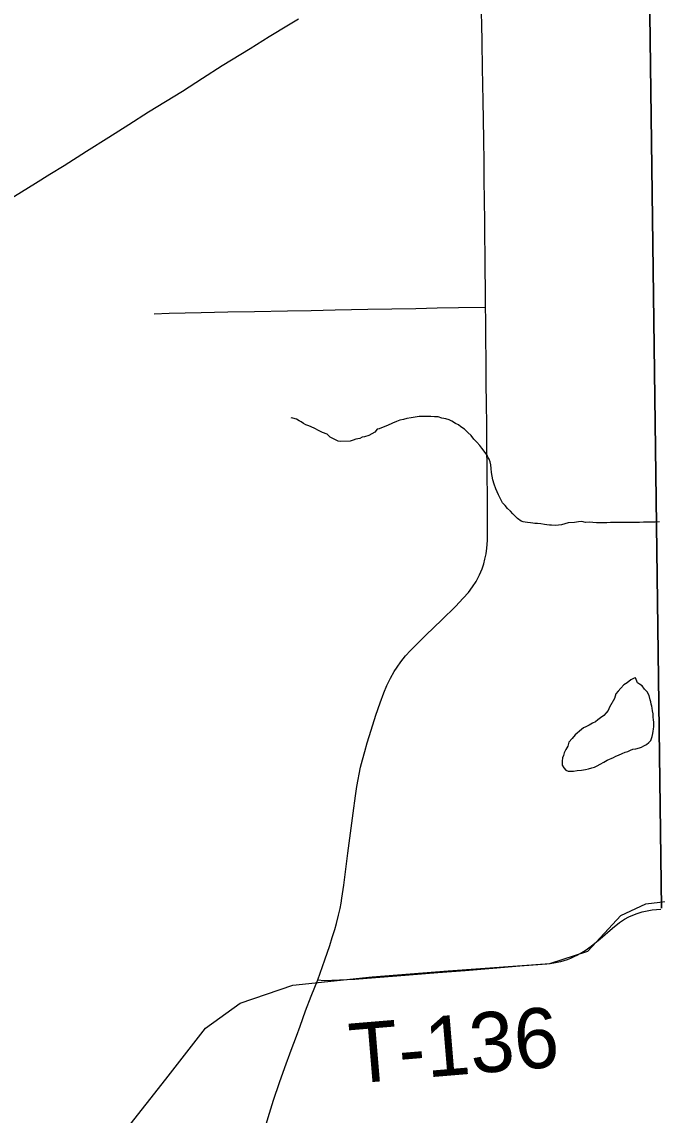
# Model space of a CAD drawing. Extents: x 103424 to 290657, y 38711 to 110967.
# Drawn here: x 146061 to 149253, y 55076 to 60565 of the extents above; entities that cross this region are included whole.
import ezdxf

# ---------------------------------------------------------------- set-up
doc = ezdxf.new("R2010")
doc.units = 0
for name, color, linetype in [('GM_X_Corporation', 7, 'Continuous'), ('GM_X_Minor_Lake', 7, 'Continuous'), ('GM_X_Minor_River', 7, 'Continuous'), ('GM_X_Rail_Line', 7, 'Continuous'), ('GM_X_State_Route', 7, 'Continuous'), ('GM_X_Township_Road', 7, 'Continuous'), ('GM_X_Township_Road_Text', 7, 'Continuous')]:
    doc.layers.add(name, color=color, linetype=linetype)

msp = doc.modelspace()

# ---------------------------------------------------------------- linework, layer by layer
at = {"layer": 'GM_X_Corporation'}
for points in [[(149274.7, 56114.3), (149214.2, 60733.4), (149097.2, 69817.3), (149097.1, 69822.5), (149073.5, 71652), (151578, 71707.7)], [(149097.2, 69817.3), (149214.2, 60733.4), (149274.7, 56114.3)]]:
    msp.add_lwpolyline(points, dxfattribs=at)
at = {"layer": 'GM_X_Minor_Lake'}
for points in [[(149144.5, 57272.3), (149138.5, 57270.1), (149120.5, 57261.6), (149102.6, 57247.1), (149086.7, 57236.7), (149070.8, 57220.2), (149057, 57203.7), (149045.2, 57191.3), (149039.6, 57167), (149014.3, 57124.1), (149006.5, 57107.7), (148996.7, 57095.4), (148984.8, 57083), (148968.9, 57070.6), (148955, 57060.2), (148943.1, 57049.8), (148929.1, 57043.5), (148911.1, 57033), (148895.1, 57024.6), (148883.1, 57020.2), (148873.2, 57012), (148863.2, 57003.7), (148851.3, 56993.3), (148841.4, 56985), (148825.6, 56966.5), (148809.9, 56948), (148804.2, 56927.7), (148794.5, 56911.3), (148786.7, 56895), (148783, 56880.8), (148777.2, 56870.6), (148775.5, 56852.4), (148776, 56832.2), (148784.3, 56820.2), (148794.7, 56808.4), (148806.9, 56802.6), (148817, 56802.8), (148833.2, 56803.1), (148851.3, 56805.5), (148873.5, 56808), (148893.6, 56810.5), (148907.7, 56814.9), (148925.8, 56819.3), (148937.8, 56823.6)], [(149144.5, 57272.3), (149138.5, 57270.1), (149120.5, 57261.6), (149102.6, 57247.1), (149086.7, 57236.7), (149070.8, 57220.2), (149057, 57203.7), (149045.2, 57191.3), (149039.6, 57167), (149014.3, 57124.1), (149006.5, 57107.7), (148996.7, 57095.4), (148984.8, 57083), (148968.9, 57070.6), (148955, 57060.2), (148943.1, 57049.8), (148929.1, 57043.5), (148911.1, 57033), (148895.1, 57024.6), (148883.1, 57020.2), (148873.2, 57012), (148863.2, 57003.7), (148851.3, 56993.3), (148841.4, 56985), (148825.6, 56966.5), (148809.9, 56948), (148804.2, 56927.7), (148794.5, 56911.3), (148786.7, 56895), (148783, 56880.8), (148777.2, 56870.6), (148775.5, 56852.4), (148776, 56832.2), (148784.3, 56820.2), (148794.7, 56808.4), (148806.9, 56802.6), (148817, 56802.8), (148833.2, 56803.1), (148851.3, 56805.5), (148873.5, 56808), (148893.6, 56810.5), (148907.7, 56814.9), (148925.8, 56819.3), (148937.8, 56823.6), (148951.8, 56829.9), (148967.8, 56838.4), (148985.8, 56848.8), (149001.8, 56857.3), (149033.8, 56872.1), (149045.8, 56878.4), (149059.8, 56882.8), (149077.8, 56891.2), (149091.9, 56897.6), (149105.9, 56901.9), (149119.9, 56908.3), (149132, 56912.6), (149146.1, 56914.9), (149164.2, 56919.4), (149174.2, 56923.6), (149186.2, 56929.9), (149200.2, 56936.3), (149212.1, 56946.7), (149222, 56957), (149225.8, 56967.1), (149227.6, 56977.3), (149231.3, 56991.5), (149233.1, 57003.6), (149234.9, 57013.8), (149236.6, 57027.9), (149236.4, 57038), (149236.2, 57048.1), (149235.9, 57060.2), (149233.6, 57074.3), (149233.3, 57090.5), (149230.9, 57106.6), (149228.6, 57118.6), (149226.4, 57128.7), (149224.1, 57138.7), (149221.9, 57150.8), (149217.6, 57160.8), (149213.1, 57182.9), (149202.6, 57200.8), (149190.2, 57214.7), (149177.7, 57230.6), (149165.4, 57240.4), (149155.2, 57246.2), (149144.5, 57272.3)], [(148937.8, 56823.6), (148951.8, 56829.9), (148967.8, 56838.4), (148985.8, 56848.8), (149001.8, 56857.3), (149033.8, 56872.1), (149045.8, 56878.4), (149059.8, 56882.8), (149077.8, 56891.2), (149091.9, 56897.6), (149105.9, 56901.9), (149119.9, 56908.3), (149132, 56912.6), (149146.1, 56914.9), (149164.2, 56919.4), (149174.2, 56923.6), (149186.2, 56929.9), (149200.2, 56936.3), (149212.1, 56946.7), (149222, 56957), (149225.8, 56967.1), (149227.6, 56977.3), (149231.3, 56991.5), (149233.1, 57003.6), (149234.9, 57013.8), (149236.6, 57027.9), (149236.4, 57038), (149236.2, 57048.1), (149235.9, 57060.2), (149233.6, 57074.3), (149233.3, 57090.5), (149230.9, 57106.6), (149228.6, 57118.6), (149226.4, 57128.7), (149224.1, 57138.7), (149221.9, 57150.8), (149217.6, 57160.8), (149213.1, 57182.9), (149202.6, 57200.8), (149190.2, 57214.7), (149177.7, 57230.6), (149165.4, 57240.4), (149155.2, 57246.2), (149144.5, 57272.3)]]:
    msp.add_lwpolyline(points, dxfattribs=at)
at = {"layer": 'GM_X_Minor_River'}
for points in [[(148134.3, 58582.8), (148116.1, 58584.4), (148095.9, 58584), (148075.7, 58583.6), (148057.5, 58583.2), (148037.4, 58580.7), (148017.3, 58576.2), (147995.1, 58573.7), (147979, 58569.4), (147960.9, 58564.9), (147942.9, 58558.5), (147922.8, 58550), (147898.8, 58539.3), (147876.8, 58530.8), (147856.7, 58522.3), (147846.7, 58520), (147834.8, 58505.6), (147804.9, 58488.8), (147782.8, 58482.3), (147770.7, 58480), (147758.7, 58473.7), (147738.6, 58469.2), (147726.6, 58464.9), (147710.5, 58460.5), (147660, 58457.4), (147649.9, 58459.2), (147633.5, 58469), (147611, 58480.6), (147594.6, 58494.3), (147572.1, 58504), (147551.7, 58513.6), (147533.3, 58523.3), (147515, 58531), (147502.7, 58536.8), (147488.5, 58542.5), (147476.2, 58548.3), (147463.9, 58556.1), (147453.7, 58561.9), (147441.4, 58569.8), (147423.1, 58575.4), (147415, 58577.3), (147415, 58575.2)], [(149265.3, 58054.2), (149243, 58053.7), (149184.5, 58052.5), (149164.3, 58052), (149144, 58051.6), (149123.9, 58051.1), (149103.7, 58050.7), (149077.4, 58052.1), (149057.1, 58051.7), (149036.9, 58051.3), (149018.8, 58050.9), (149000.6, 58050.5), (148984.4, 58050.1), (148966.2, 58049.7), (148948.1, 58049.3), (148929.8, 58051), (148911.6, 58052.6), (148893.4, 58052.2), (148875.2, 58055.8), (148859, 58055.5), (148838.9, 58051), (148806.6, 58050.3), (148772.4, 58039.5), (148742.2, 58036.8), (148721.9, 58038.4), (148711.8, 58038.1), (148699.7, 58039.9), (148687.5, 58041.7), (148669.2, 58045.3), (148653, 58047), (148638.9, 58046.7), (148628.8, 58048.4), (148616.6, 58050.2), (148602.4, 58051.9), (148590.3, 58053.7), (148580.1, 58055.5), (148570, 58057.3), (148551.5, 58071), (148541.2, 58080.9), (148528.7, 58094.7), (148516.3, 58108.6), (148501.9, 58122.4), (148489.5, 58136.3), (148477, 58150.1), (148466.5, 58170.1), (148456, 58190.1), (148443.2, 58220.1), (148434.6, 58244.1), (148428.1, 58266.2), (148423.7, 58284.2), (148421.2, 58302.4), (148418.8, 58322.5), (148418.4, 58340.7), (148414, 58356.7), (148409.7, 58368.7), (148403.4, 58378.7), (148399.2, 58388.7), (148372.2, 58424.5), (148361.7, 58438.4), (148347.3, 58454.2), (148332.8, 58470), (148318.3, 58487.9), (148301.7, 58503.7), (148285.2, 58519.5), (148266.8, 58531.2), (148254.5, 58541), (148240.2, 58548.8), (148221.7, 58560.5), (148207.5, 58566.2), (148191.2, 58571.9), (148170.9, 58575.5), (148152.6, 58581.2), (148134.3, 58582.8)]]:
    msp.add_lwpolyline(points, dxfattribs=at)
at = {"layer": 'GM_X_Rail_Line'}
msp.add_lwpolyline([(146505.7, 54902.5), (146783.9, 55255.5), (146983.2, 55513), (147157.5, 55637.6), (147423.3, 55729), (147821.8, 55770.5), (148203.8, 55799.6), (148714.5, 55836.9), (148905.5, 55899.2), (149071.5, 56077.8), (149196.1, 56136), (149366.3, 56156.7)], dxfattribs=at)
at = {"layer": 'GM_X_State_Route'}
for points in [[(148373.8, 60461.2), (148373.4, 60482.3), (148372.2, 60536.1), (148370.3, 60624), (148368.9, 60684.8), (148367.7, 60746.2), (148366.9, 60856.3), (148366.2, 60966.4), (148365.4, 61012.8)], [(145385.3, 59293), (145430.6, 59322), (145532.7, 59384.8), (145610.3, 59433.4), (145687.9, 59482.1), (145768.3, 59531.9), (145848.8, 59581.7), (145989.1, 59668.6), (146129.5, 59755.5), (146201.5, 59800.2), (146273.6, 59844.8), (146386.1, 59915.7), (146498.6, 59986.6), (146598.1, 60049.6), (146697.5, 60112.7), (146782.9, 60165.4), (146868.2, 60218), (146967.9, 60281.7), (147067.5, 60345.5), (147208, 60432.1), (147304.2, 60491.4), (147400.5, 60550.7), (147451.3, 60581)], [(145385.3, 59293), (145430.6, 59322), (145532.7, 59384.8), (145610.3, 59433.4), (145687.9, 59482.1), (145768.3, 59531.9), (145848.8, 59581.7), (145989.1, 59668.6), (146129.5, 59755.5), (146201.5, 59800.2), (146273.6, 59844.8), (146386.1, 59915.7), (146498.6, 59986.6), (146598.1, 60049.6), (146697.5, 60112.7), (146782.9, 60165.4), (146868.2, 60218), (146967.9, 60281.7), (147067.5, 60345.5), (147208, 60432.1), (147304.2, 60491.4), (147400.5, 60550.7), (147451.3, 60581)], [(147279.2, 54997.2), (147305.2, 55085.4), (147325.5, 55150.9), (147355.2, 55240.2), (147381.7, 55314.1), (147413.9, 55401.1), (147440.4, 55472.3), (147459.1, 55522.6), (147486.6, 55599.4), (147515.3, 55672.4), (147547.6, 55754.3), (147582.9, 55856.2), (147607.8, 55927.4), (147621, 55967), (147633.4, 56008.6), (147642.1, 56038.2), (147652.7, 56080.5), (147659.7, 56113), (147665, 56140.3), (147669.4, 56165.8), (147679, 56230.9), (147689.6, 56310.1), (147699.1, 56391.6), (147712.6, 56491.5), (147725.8, 56591.5), (147736.9, 56678.6), (147744.1, 56726.3), (147750.3, 56761.1), (147755.6, 56787.9), (147763.5, 56822.2), (147772.3, 56860), (147783.8, 56901.4), (147796.1, 56944.5), (147816.5, 57008.7), (147840.4, 57084.1), (147862, 57145.1), (147880.4, 57195.5), (147895.5, 57233.1), (147913.1, 57270.1), (147932.4, 57302.6), (147947.4, 57325.5), (147965.9, 57351.9), (147989.6, 57381.8), (148014.3, 57409.1), (148090.7, 57484.9), (148171.4, 57562.9), (148240, 57629.2), (148278, 57671.1), (148304.9, 57700.6), (148325.7, 57727.6), (148344.2, 57755.7), (148360.9, 57789.2), (148373.3, 57819.1), (148382.1, 57843.7), (148388, 57866.8), (148393.4, 57893.3), (148397.8, 57922.3), (148401, 57960.2), (148401.6, 57989.6), (148401.1, 58082.5), (148400.7, 58175.4), (148399.6, 58296), (148398, 58458.7), (148397.1, 58545), (148396.1, 58645.3), (148395, 58751.7), (148394, 58854.7), (148392.6, 58984.9), (148391.8, 59068.5), (148391.2, 59132.2), (148390.1, 59228.6), (148389.2, 59316.6), (148388.7, 59400.7), (148388.2, 59484.7), (148387.3, 59564.7), (148386, 59667.7), (148384.8, 59772.4), (148383.7, 59862.1), (148382.4, 59972.1), (148381.2, 60074.2), (148379.4, 60166.6), (148377.8, 60250.5), (148376.2, 60334.5), (148373.8, 60461.2)]]:
    msp.add_lwpolyline(points, dxfattribs=at)
at = {"layer": 'GM_X_Township_Road'}
for points in [[(146725.3, 59099.3), (146800.9, 59102.8), (146962.4, 59105.9), (147096.3, 59108.5), (147230.1, 59111.1), (147395.1, 59114.3), (147515.1, 59116.6), (147635, 59118.9), (147800.1, 59122.1), (147920.3, 59124.4), (148040.6, 59126.7), (148147.8, 59128.8), (148254.9, 59130.8), (148391.2, 59132.2)], [(147547.6, 55754.3), (147580.3, 55752.3), (147734.3, 55758.9), (147860.5, 55768.3), (147986.7, 55777.8), (148151.2, 55791.1), (148289.5, 55802.3), (148427.6, 55813.6), (148563.2, 55824.6), (148698.7, 55835.5), (148716.6, 55837.3), (148734.2, 55839.9), (148751.6, 55843.2), (148769, 55847.3), (148785.9, 55852.3), (148802.7, 55858), (148819.3, 55864.4), (148835.7, 55871.6), (148851.6, 55879.5), (148866.9, 55888.1), (148891.7, 55902.1), (148921.8, 55923.7), (148966.4, 55960.4), (149029.2, 56014.4), (149064.7, 56042.3), (149090.2, 56059.3), (149111.9, 56070.9), (149130.8, 56079.6), (149153.7, 56088.8), (149178.4, 56096.5), (149195, 56100.5), (149211.9, 56103.6), (149229, 56106), (149249.4, 56108.4), (149271.7, 56109.1)]]:
    msp.add_lwpolyline(points, dxfattribs=at)

# ---------------------------------------------------------------- texts
at = {"layer": 'GM_X_Township_Road_Text'}
msp.add_text('T-136', height=301.87, rotation=4.7654, dxfattribs=at).set_placement((147718.7, 55233.2))

doc.saveas('drawing.dxf')
